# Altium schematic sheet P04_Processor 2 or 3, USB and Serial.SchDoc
size 513 x 386 mm
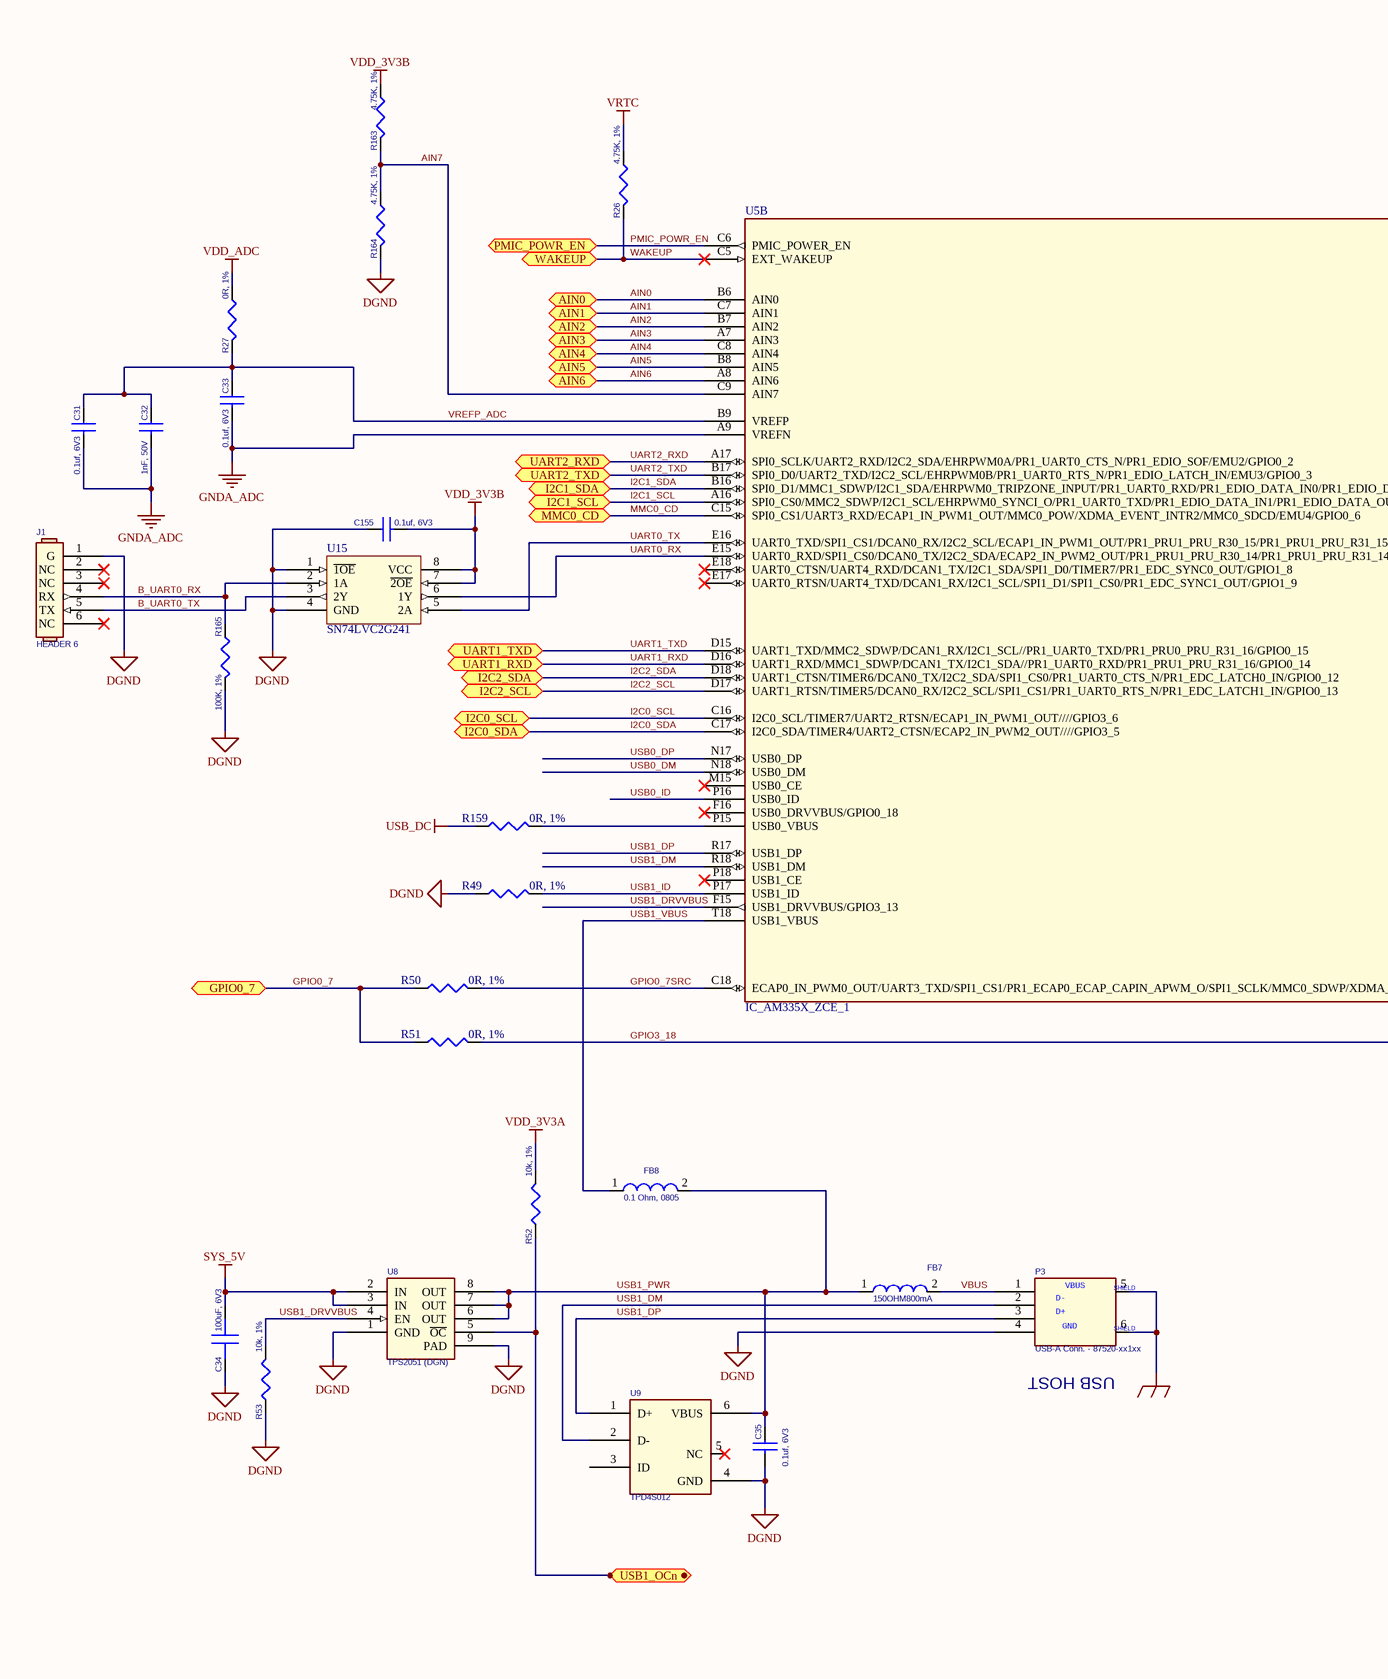
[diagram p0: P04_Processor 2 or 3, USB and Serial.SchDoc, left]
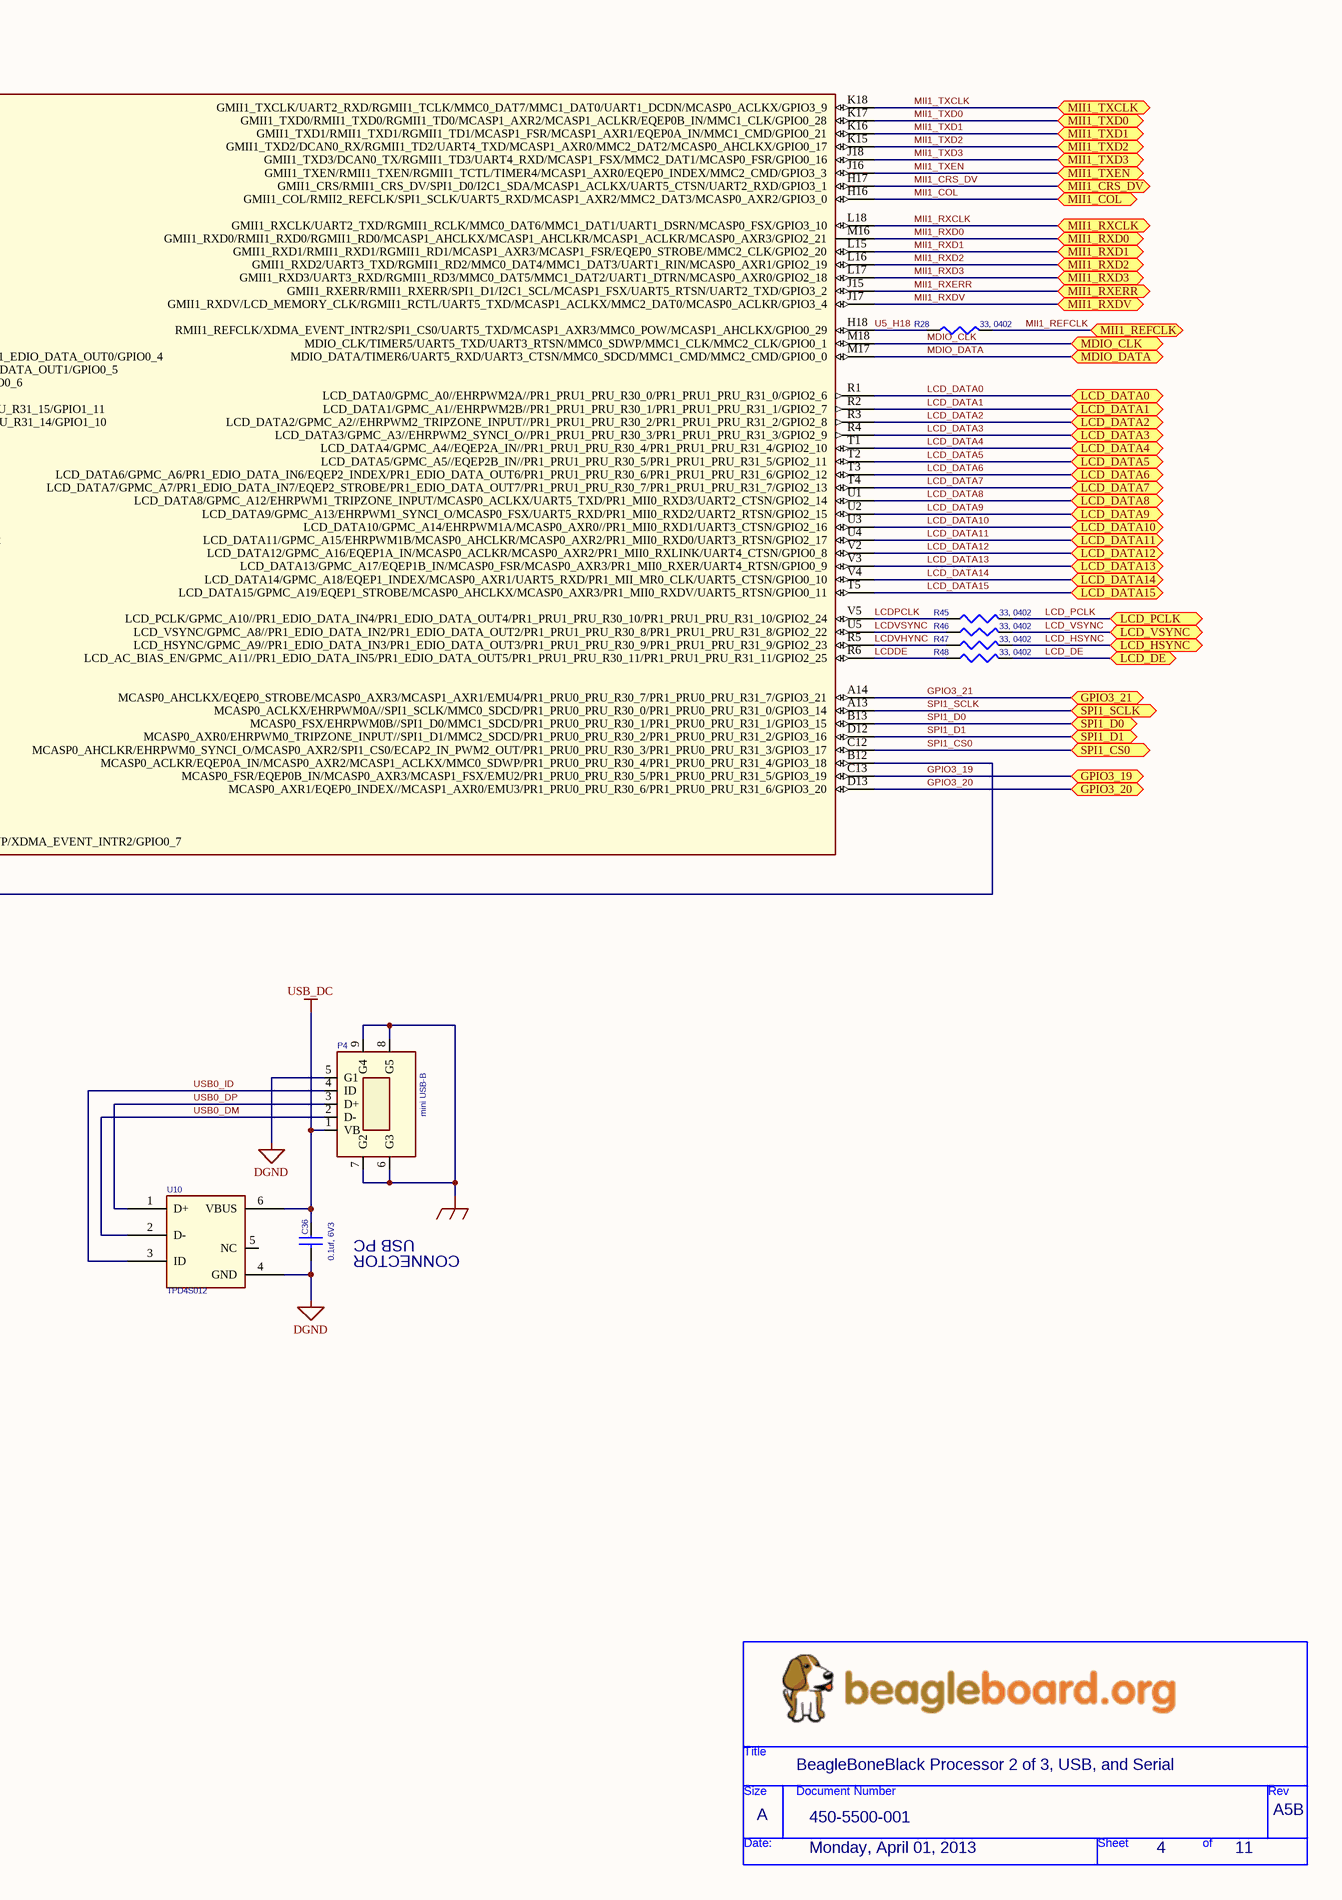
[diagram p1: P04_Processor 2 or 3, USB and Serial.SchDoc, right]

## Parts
*  Page Create Date: Monday, April 01, 2013  Doc: 450-5500-001  RevCode: A5B  Title: BeagleBoneBlack Processor 2 of 3, USB, and Serial  Page Size: A  Page Number: 4  Page Count: 11  (hidden comment: BeagleBoard_org)  (graphical)
C31  0.1uf, 6V3  [402]
C32  1nF, 50V  [402]
C33  0.1uf, 6V3  [402]
C34  100uF, 6V3  [RD205SMD_250D]
C35  0.1uf, 6V3  [402]
C36  0.1uf, 6V3  [402]
C155  0.1uf, 6V3  [402]
FB7  150OHM800mA  [SM-7351-IND-0805]
FB8  0.1 Ohm, 0805  [SM-7351-IND-0805]
J1  HEADER 6  [SIP6]
P3  USB-A Conn. - 87520-xx1xx  [usb_a_sh]
P4  mini USB-B  [USB5MINI_4SHIELDED_SMD-5]
R26  4.75K, 1%  [402]
R27  0R, 1%  [402]
R28  33, 0402  [402]
R45  33, 0402  [402]
R46  33, 0402  [402]
R47  33, 0402  [402]
R48  33, 0402  [402]
R49  0R, 1%  [402]
R50  0R, 1%  [402]
R51  0R, 1%  [402]
R52  10k, 1%  [402]
R53  10k, 1%  [402]
R159  0R, 1%  [402]
R163  4.75K, 1%  [402]
R164  4.75K, 1%  [402]
R165  100K, 1%  [402]
U5  IC_AM335X_ZCE_1  [am33xx_15x15]  (part B of 3)
U8  TPS2051 (DGN)  [DGN-16X60]
U9  TPD4S012  [U_6_DRY]
U10  TPD4S012  [U_6_DRY]
U15  SN74LVC2G241  [U_8_DCU]

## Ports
AIN0, AIN1, AIN2, AIN3, AIN4, AIN5, AIN6, GPIO0_7, GPIO3_19, GPIO3_20, GPIO3_21, I2C0_SCL, I2C0_SDA, I2C1_SCL, I2C1_SDA, I2C2_SCL, I2C2_SDA, LCD_DATA0, LCD_DATA1, LCD_DATA2, LCD_DATA3, LCD_DATA4, LCD_DATA5, LCD_DATA6, LCD_DATA7, LCD_DATA8, LCD_DATA9, LCD_DATA10, LCD_DATA11, LCD_DATA12, LCD_DATA13, LCD_DATA14, LCD_DATA15, LCD_DE, LCD_HSYNC, LCD_PCLK, LCD_VSYNC, MDIO_CLK, MDIO_DATA, MII1_COL, MII1_CRS_DV, MII1_REFCLK, MII1_RXCLK, MII1_RXD0, MII1_RXD1, MII1_RXD2, MII1_RXD3, MII1_RXDV, MII1_RXERR, MII1_TXCLK, MII1_TXD0, MII1_TXD1, MII1_TXD2, MII1_TXD3, MII1_TXEN, MMC0_CD, PMIC_POWR_EN, SPI1_CS0, SPI1_D0, SPI1_D1, SPI1_SCLK, UART1_RXD, UART1_TXD, UART2_RXD, UART2_TXD, USB1_OCn, WAKEUP

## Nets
DGND: C34.2 C35.2 C36.2 C155.1 J1.1(G) P3.4(P4) P4.5(G1) R49.1 R53.2(P2) R164.2 R165.2 U8.1(GND) U8.9(PAD) U9.4(GND) U10.4(GND) U15.1(~{1OE}) U15.4(GND)
GND_EARTH: P3.5(SHELD1) P3.6(PAD4) P4.6(G3) P4.7(G2) P4.8(G5) P4.9(G4)
GNDA_ADC: C31.2 C32.2 C33.2 U5.A9(VREFN)
SYS_5V: C34.1 U8.2(IN) U8.3(IN)
USB_DC: C36.1 P4.1(VB) R159.1 U10.6(VBUS)
VDD_3V3A: R52.1(P1)
VDD_3V3B: C155.2 R163.1 U15.7(~{2OE}) U15.8(VCC)
VDD_ADC: R27.1
VRTC: R26.1
AIN0: U5.B6(AIN0) ; port AIN0
AIN1: U5.C7(AIN1) ; port AIN1
AIN2: U5.B7(AIN2) ; port AIN2
AIN3: U5.A7(AIN3) ; port AIN3
AIN4: U5.C8(AIN4) ; port AIN4
AIN5: U5.B8(AIN5) ; port AIN5
AIN6: U5.A8(AIN6) ; port AIN6
AIN7: R163.2 R164.1 U5.C9(AIN7)
B_UART0_RX: J1.4(RX) R165.1 U15.2(1A)
B_UART0_TX: J1.5(TX) U15.3(2Y)
GPIO0_7: R50.1 R51.1 ; port GPIO0_7
GPIO0_7SRC: R50.2 U5.C18(ECAP0_IN_PWM0_OUT/UART3_TXD/SPI1_CS1/PR1_ECAP0_ECAP_CAPIN_APWM_O/SPI1_SCLK/MMC0_SDWP/XDMA_EVENT_INTR2/GPIO0_7)
GPIO3_18: R51.2 U5.B12(MCASP0_ACLKR/EQEP0A_IN/MCASP0_AXR2/MCASP1_ACLKX/MMC0_SDWP/PR1_PRU0_PRU_R30_4/PR1_PRU0_PRU_R31_4/GPIO3_18)
GPIO3_19: U5.C13(MCASP0_FSR/EQEP0B_IN/MCASP0_AXR3/MCASP1_FSX/EMU2/PR1_PRU0_PRU_R30_5/PR1_PRU0_PRU_R31_5/GPIO3_19) ; port GPIO3_19
GPIO3_20: U5.D13(MCASP0_AXR1/EQEP0_INDEX//MCASP1_AXR0/EMU3/PR1_PRU0_PRU_R30_6/PR1_PRU0_PRU_R31_6/GPIO3_20) ; port GPIO3_20
GPIO3_21: U5.A14(MCASP0_AHCLKX/EQEP0_STROBE/MCASP0_AXR3/MCASP1_AXR1/EMU4/PR1_PRU0_PRU_R30_7/PR1_PRU0_PRU_R31_7/GPIO3_21) ; port GPIO3_21
I2C0_SCL: U5.C16(I2C0_SCL/TIMER7/UART2_RTSN/ECAP1_IN_PWM1_OUT////GPIO3_6) ; port I2C0_SCL
I2C0_SDA: U5.C17(I2C0_SDA/TIMER4/UART2_CTSN/ECAP2_IN_PWM2_OUT////GPIO3_5) ; port I2C0_SDA
I2C1_SCL: U5.A16(SPI0_CS0/MMC2_SDWP/I2C1_SCL/EHRPWM0_SYNCI_O/PR1_UART0_TXD/PR1_EDIO_DATA_IN1/PR1_EDIO_DATA_OUT1/GPIO0_5) ; port I2C1_SCL
I2C1_SDA: U5.B16(SPI0_D1/MMC1_SDWP/I2C1_SDA/EHRPWM0_TRIPZONE_INPUT/PR1_UART0_RXD/PR1_EDIO_DATA_IN0/PR1_EDIO_DATA_OUT0/GPIO0_4) ; port I2C1_SDA
I2C2_SCL: U5.D17(UART1_RTSN/TIMER5/DCAN0_RX/I2C2_SCL/SPI1_CS1/PR1_UART0_RTS_N/PR1_EDC_LATCH1_IN/GPIO0_13) ; port I2C2_SCL
I2C2_SDA: U5.D18(UART1_CTSN/TIMER6/DCAN0_TX/I2C2_SDA/SPI1_CS0/PR1_UART0_CTS_N/PR1_EDC_LATCH0_IN/GPIO0_12) ; port I2C2_SDA
LCD_DATA0: U5.R1(LCD_DATA0/GPMC_A0//EHRPWM2A//PR1_PRU1_PRU_R30_0/PR1_PRU1_PRU_R31_0/GPIO2_6) ; port LCD_DATA0
LCD_DATA1: U5.R2(LCD_DATA1/GPMC_A1//EHRPWM2B//PR1_PRU1_PRU_R30_1/PR1_PRU1_PRU_R31_1/GPIO2_7) ; port LCD_DATA1
LCD_DATA2: U5.R3(LCD_DATA2/GPMC_A2//EHRPWM2_TRIPZONE_INPUT//PR1_PRU1_PRU_R30_2/PR1_PRU1_PRU_R31_2/GPIO2_8) ; port LCD_DATA2
LCD_DATA3: U5.R4(LCD_DATA3/GPMC_A3//EHRPWM2_SYNCI_O//PR1_PRU1_PRU_R30_3/PR1_PRU1_PRU_R31_3/GPIO2_9) ; port LCD_DATA3
LCD_DATA4: U5.T1(LCD_DATA4/GPMC_A4//EQEP2A_IN//PR1_PRU1_PRU_R30_4/PR1_PRU1_PRU_R31_4/GPIO2_10) ; port LCD_DATA4
LCD_DATA5: U5.T2(LCD_DATA5/GPMC_A5//EQEP2B_IN//PR1_PRU1_PRU_R30_5/PR1_PRU1_PRU_R31_5/GPIO2_11) ; port LCD_DATA5
LCD_DATA6: U5.T3(LCD_DATA6/GPMC_A6/PR1_EDIO_DATA_IN6/EQEP2_INDEX/PR1_EDIO_DATA_OUT6/PR1_PRU1_PRU_R30_6/PR1_PRU1_PRU_R31_6/GPIO2_12) ; port LCD_DATA6
LCD_DATA7: U5.T4(LCD_DATA7/GPMC_A7/PR1_EDIO_DATA_IN7/EQEP2_STROBE/PR1_EDIO_DATA_OUT7/PR1_PRU1_PRU_R30_7/PR1_PRU1_PRU_R31_7/GPIO2_13) ; port LCD_DATA7
LCD_DATA8: U5.U1(LCD_DATA8/GPMC_A12/EHRPWM1_TRIPZONE_INPUT/MCASP0_ACLKX/UART5_TXD/PR1_MII0_RXD3/UART2_CTSN/GPIO2_14) ; port LCD_DATA8
LCD_DATA9: U5.U2(LCD_DATA9/GPMC_A13/EHRPWM1_SYNCI_O/MCASP0_FSX/UART5_RXD/PR1_MII0_RXD2/UART2_RTSN/GPIO2_15) ; port LCD_DATA9
LCD_DATA10: U5.U3(LCD_DATA10/GPMC_A14/EHRPWM1A/MCASP0_AXR0//PR1_MII0_RXD1/UART3_CTSN/GPIO2_16) ; port LCD_DATA10
LCD_DATA11: U5.U4(LCD_DATA11/GPMC_A15/EHRPWM1B/MCASP0_AHCLKR/MCASP0_AXR2/PR1_MII0_RXD0/UART3_RTSN/GPIO2_17) ; port LCD_DATA11
LCD_DATA12: U5.V2(LCD_DATA12/GPMC_A16/EQEP1A_IN/MCASP0_ACLKR/MCASP0_AXR2/PR1_MII0_RXLINK/UART4_CTSN/GPIO0_8) ; port LCD_DATA12
LCD_DATA13: U5.V3(LCD_DATA13/GPMC_A17/EQEP1B_IN/MCASP0_FSR/MCASP0_AXR3/PR1_MII0_RXER/UART4_RTSN/GPIO0_9) ; port LCD_DATA13
LCD_DATA14: U5.V4(LCD_DATA14/GPMC_A18/EQEP1_INDEX/MCASP0_AXR1/UART5_RXD/PR1_MII_MR0_CLK/UART5_CTSN/GPIO0_10) ; port LCD_DATA14
LCD_DATA15: U5.T5(LCD_DATA15/GPMC_A19/EQEP1_STROBE/MCASP0_AHCLKX/MCASP0_AXR3/PR1_MII0_RXDV/UART5_RTSN/GPIO0_11) ; port LCD_DATA15
LCD_DE: R48.2 ; port LCD_DE
LCD_HSYNC: R47.2 ; port LCD_HSYNC
LCD_PCLK: R45.2 ; port LCD_PCLK
LCD_VSYNC: R46.2 ; port LCD_VSYNC
LCDDE: R48.1 U5.R6(LCD_AC_BIAS_EN/GPMC_A11//PR1_EDIO_DATA_IN5/PR1_EDIO_DATA_OUT5/PR1_PRU1_PRU_R30_11/PR1_PRU1_PRU_R31_11/GPIO2_25)
LCDPCLK: R45.1 U5.V5(LCD_PCLK/GPMC_A10//PR1_EDIO_DATA_IN4/PR1_EDIO_DATA_OUT4/PR1_PRU1_PRU_R30_10/PR1_PRU1_PRU_R31_10/GPIO2_24)
LCDVHYNC: R47.1 U5.R5(LCD_HSYNC/GPMC_A9//PR1_EDIO_DATA_IN3/PR1_EDIO_DATA_OUT3/PR1_PRU1_PRU_R30_9/PR1_PRU1_PRU_R31_9/GPIO2_23)
LCDVSYNC: R46.1 U5.U5(LCD_VSYNC/GPMC_A8//PR1_EDIO_DATA_IN2/PR1_EDIO_DATA_OUT2/PR1_PRU1_PRU_R30_8/PR1_PRU1_PRU_R31_8/GPIO2_22)
MDIO_CLK: U5.M18(MDIO_CLK/TIMER5/UART5_TXD/UART3_RTSN/MMC0_SDWP/MMC1_CLK/MMC2_CLK/GPIO0_1) ; port MDIO_CLK
MDIO_DATA: U5.M17(MDIO_DATA/TIMER6/UART5_RXD/UART3_CTSN/MMC0_SDCD/MMC1_CMD/MMC2_CMD/GPIO0_0) ; port MDIO_DATA
MII1_COL: U5.H16(GMII1_COL/RMII2_REFCLK/SPI1_SCLK/UART5_RXD/MCASP1_AXR2/MMC2_DAT3/MCASP0_AXR2/GPIO3_0) ; port MII1_COL
MII1_CRS_DV: U5.H17(GMII1_CRS/RMII1_CRS_DV/SPI1_D0/I2C1_SDA/MCASP1_ACLKX/UART5_CTSN/UART2_RXD/GPIO3_1) ; port MII1_CRS_DV
MII1_REFCLK: R28.2 ; port MII1_REFCLK
MII1_RXCLK: U5.L18(GMII1_RXCLK/UART2_TXD/RGMII1_RCLK/MMC0_DAT6/MMC1_DAT1/UART1_DSRN/MCASP0_FSX/GPIO3_10) ; port MII1_RXCLK
MII1_RXD0: U5.M16(GMII1_RXD0/RMII1_RXD0/RGMII1_RD0/MCASP1_AHCLKX/MCASP1_AHCLKR/MCASP1_ACLKR/MCASP0_AXR3/GPIO2_21) ; port MII1_RXD0
MII1_RXD1: U5.L15(GMII1_RXD1/RMII1_RXD1/RGMII1_RD1/MCASP1_AXR3/MCASP1_FSR/EQEP0_STROBE/MMC2_CLK/GPIO2_20) ; port MII1_RXD1
MII1_RXD2: U5.L16(GMII1_RXD2/UART3_TXD/RGMII1_RD2/MMC0_DAT4/MMC1_DAT3/UART1_RIN/MCASP0_AXR1/GPIO2_19) ; port MII1_RXD2
MII1_RXD3: U5.L17(GMII1_RXD3/UART3_RXD/RGMII1_RD3/MMC0_DAT5/MMC1_DAT2/UART1_DTRN/MCASP0_AXR0/GPIO2_18) ; port MII1_RXD3
MII1_RXDV: U5.J17(GMII1_RXDV/LCD_MEMORY_CLK/RGMII1_RCTL/UART5_TXD/MCASP1_ACLKX/MMC2_DAT0/MCASP0_ACLKR/GPIO3_4) ; port MII1_RXDV
MII1_RXERR: U5.J15(GMII1_RXERR/RMII1_RXERR/SPI1_D1/I2C1_SCL/MCASP1_FSX/UART5_RTSN/UART2_TXD/GPIO3_2) ; port MII1_RXERR
MII1_TXCLK: U5.K18(GMII1_TXCLK/UART2_RXD/RGMII1_TCLK/MMC0_DAT7/MMC1_DAT0/UART1_DCDN/MCASP0_ACLKX/GPIO3_9) ; port MII1_TXCLK
MII1_TXD0: U5.K17(GMII1_TXD0/RMII1_TXD0/RGMII1_TD0/MCASP1_AXR2/MCASP1_ACLKR/EQEP0B_IN/MMC1_CLK/GPIO0_28) ; port MII1_TXD0
MII1_TXD1: U5.K16(GMII1_TXD1/RMII1_TXD1/RGMII1_TD1/MCASP1_FSR/MCASP1_AXR1/EQEP0A_IN/MMC1_CMD/GPIO0_21) ; port MII1_TXD1
MII1_TXD2: U5.K15(GMII1_TXD2/DCAN0_RX/RGMII1_TD2/UART4_TXD/MCASP1_AXR0/MMC2_DAT2/MCASP0_AHCLKX/GPIO0_17) ; port MII1_TXD2
MII1_TXD3: U5.J18(GMII1_TXD3/DCAN0_TX/RGMII1_TD3/UART4_RXD/MCASP1_FSX/MMC2_DAT1/MCASP0_FSR/GPIO0_16) ; port MII1_TXD3
MII1_TXEN: U5.J16(GMII1_TXEN/RMII1_TXEN/RGMII1_TCTL/TIMER4/MCASP1_AXR0/EQEP0_INDEX/MMC2_CMD/GPIO3_3) ; port MII1_TXEN
MMC0_CD: U5.C15(SPI0_CS1/UART3_RXD/ECAP1_IN_PWM1_OUT/MMC0_POW/XDMA_EVENT_INTR2/MMC0_SDCD/EMU4/GPIO0_6) ; port MMC0_CD
PMIC_POWR_EN: U5.C6(PMIC_POWER_EN) ; port PMIC_POWR_EN
SPI1_CS0: U5.C12(MCASP0_AHCLKR/EHRPWM0_SYNCI_O/MCASP0_AXR2/SPI1_CS0/ECAP2_IN_PWM2_OUT/PR1_PRU0_PRU_R30_3/PR1_PRU0_PRU_R31_3/GPIO3_17) ; port SPI1_CS0
SPI1_D0: U5.B13(MCASP0_FSX/EHRPWM0B//SPI1_D0/MMC1_SDCD/PR1_PRU0_PRU_R30_1/PR1_PRU0_PRU_R31_1/GPIO3_15) ; port SPI1_D0
SPI1_D1: U5.D12(MCASP0_AXR0/EHRPWM0_TRIPZONE_INPUT//SPI1_D1/MMC2_SDCD/PR1_PRU0_PRU_R30_2/PR1_PRU0_PRU_R31_2/GPIO3_16) ; port SPI1_D1
SPI1_SCLK: U5.A13(MCASP0_ACLKX/EHRPWM0A//SPI1_SCLK/MMC0_SDCD/PR1_PRU0_PRU_R30_0/PR1_PRU0_PRU_R31_0/GPIO3_14) ; port SPI1_SCLK
U5_H18: R28.1 U5.H18(RMII1_REFCLK/XDMA_EVENT_INTR2/SPI1_CS0/UART5_TXD/MCASP1_AXR3/MMC0_POW/MCASP1_AHCLKX/GPIO0_29)
UART0_RX: U5.E15(UART0_RXD/SPI1_CS0/DCAN0_TX/I2C2_SDA/ECAP2_IN_PWM2_OUT/PR1_PRU1_PRU_R30_14/PR1_PRU1_PRU_R31_14/GPIO1_10) U15.6(1Y)
UART0_TX: U5.E16(UART0_TXD/SPI1_CS1/DCAN0_RX/I2C2_SCL/ECAP1_IN_PWM1_OUT/PR1_PRU1_PRU_R30_15/PR1_PRU1_PRU_R31_15/GPIO1_11) U15.5(2A)
UART1_RXD: U5.D16(UART1_RXD/MMC1_SDWP/DCAN1_TX/I2C1_SDA//PR1_UART0_RXD/PR1_PRU1_PRU_R31_16/GPIO0_14) ; port UART1_RXD
UART1_TXD: U5.D15(UART1_TXD/MMC2_SDWP/DCAN1_RX/I2C1_SCL//PR1_UART0_TXD/PR1_PRU0_PRU_R31_16/GPIO0_15) ; port UART1_TXD
UART2_RXD: U5.A17(SPI0_SCLK/UART2_RXD/I2C2_SDA/EHRPWM0A/PR1_UART0_CTS_N/PR1_EDIO_SOF/EMU2/GPIO0_2) ; port UART2_RXD
UART2_TXD: U5.B17(SPI0_D0/UART2_TXD/I2C2_SCL/EHRPWM0B/PR1_UART0_RTS_N/PR1_EDIO_LATCH_IN/EMU3/GPIO0_3) ; port UART2_TXD
USB0_DM: P4.2(D-) U5.N18(USB0_DM) U10.2(D-)
USB0_DP: P4.3(D+) U5.N17(USB0_DP) U10.1(D+)
USB0_ID: P4.4(ID) U5.P16(USB0_ID) U10.3(ID)
USB1_DM: P3.2(P2) U5.R18(USB1_DM) U9.2(D-)
USB1_DP: P3.3(P3) U5.R17(USB1_DP) U9.1(D+)
USB1_DRVVBUS: R53.1(P1) U5.F15(USB1_DRVVBUS/GPIO3_13) U8.4(EN)
USB1_ID: R49.2 U5.P17(USB1_ID)
USB1_OCn: R52.2(P2) U8.5(~{OC}) ; port USB1_OCn
USB1_PWR: C35.1 FB7.1 FB8.2 U8.6(OUT) U8.7(OUT) U8.8(OUT) U9.6(VBUS)
USB1_VBUS: FB8.1 U5.T18(USB1_VBUS)
VBUS: FB7.2 P3.1(P1)
VREFP_ADC: C31.1 C32.1 C33.1 R27.2 U5.B9(VREFP)
WAKEUP: R26.2 U5.C5(EXT_WAKEUP) ; port WAKEUP
NetR159_2: R159.2 U5.P15(USB0_VBUS)

Not connected (* = marked no-connect by the designer): J1 2(NC)* 3(NC)* 6(NC)*; U5 E17(UART0_RTSN/UART4_TXD/DCAN1_RX/I2C1_SCL/SPI1_D1/SPI1_CS0/PR1_EDC_SYNC1_OUT/GPIO1_9)* E18(UART0_CTSN/UART4_RXD/DCAN1_TX/I2C1_SDA/SPI1_D0/TIMER7/PR1_EDC_SYNC0_OUT/GPIO1_8)* F16(USB0_DRVVBUS/GPIO0_18)* M15(USB0_CE)* P18(USB1_CE)*; U9 3(ID) 5(NC)*; U10 5(NC)

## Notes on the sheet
- (near P3) USB HOST
- USB PC
- CONNECTOR

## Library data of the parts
C31 C33 C35 C36 C155 = CAP_0.1uF_X7R_16V_10% 0402: CAP CER 0.1UF 6.3V 10% X5R 0402; Manufacturer: TDK Corporation; Manufacturer Part Number: C1005X5R0J104K050BA; Capacitance: 0.1µF
C32 = CAP_0.001_X7R_50V_5%_0402: CAP CER 1000PF 16V 10% X7R 0402; Manufacturer: Yageo; Manufacturer Part Number: CC0402KRX7R7BB102
C34 = CAP SMD: CAP ALUM 100UF 6.3V 20% SMD; Manufacturer: Cornell Dubilier Electronics (CDE); Manufacturer Part Number: AVE107M06D16T-F; Capacitance: 100µF; Lifetime @ Temp.: 2000 Hrs @ 85°C; Ripple Current: 120mA; ESR (Equivalent Series Resistance): 4.64 Ohm; Surface Mount Land Size: 0.260" L x 0.260" W (6.60mm x 6.60mm)
FB7 = FER_180_200_0: FERRITE 800MA 150 OHM 0805 SMD; PartName: FerriteBead150ohm800mA; Mfr: Steward; MfrNum: LI0805H151R-10; TIIntPartnumber: 1L0010; Manufacturer: Laird-Signal Integrity Products; Vendor: Digikey; Impedance @ Frequency: 150 Ohm @ 100MHz; DC Resistance (DCR): 150 mOhm Max; Filter Type: Differential Mode - Single
FB8 = FER_180_200_0: RES .10 OHM 1/8W 5% 0805; Manufacturer: CTS Resistor Products; Manufacturer Part Number: 73L3R10J; Resistance (Ohms): 0.1; Power (Watts): 0.125W, 1/8W; Temperature Coefficient: ±200ppm/°C
J1 = HDR_6x1: CONN HEADER 6POS, VERTICAL,  .100 STR TIN; Manufacturer: Samtec Inc; Manufacturer Part Number: FTR-110-03-G-D-06; Connector Type: Unshrouded; Number of Positions: 20; Number of Positions Loaded: 19; Pitch: 0.050" (1.27mm); Row Spacing: 0.100" (2.54mm)
P3 = CONN_54819-0578_2: CONN RCPT USB TYPE A R/A PCB; Manufacturer: FCI; Manufacturer Part Number: 87520-0010BLF; CLASS: IO; TN: 224-0234-000; Number of Contacts: 4; Gender: Receptacle; Specifications: USB 2.0
P4 = MINI-USB-AB-SOCKET: CONN RCPT USB MINI B R/A SMD; Manufacturer: KYCON; Manufacturer Part Number: 0565790576; Order# 2: C-440247; ATLStockNo1: 4500.0223; Order#: KMAB-SMT-5S-S-30TR; Connector Type: USB - mini AB; Number of Contacts: 5; Gender: Receptacle; Specifications: USB 2.0 OTG
R26 R163 R164 = RES_4.75K_1/16W_1%_0402: RES 4.75K OHM 1/16W 1% 0402 SMD; Manufacturer: Stackpole Electronics Inc; Manufacturer Part Number: RMCF0402FT4K75; Power (Watts): 0.063W, 1/16W; Temperature Coefficient: ±100ppm/°C
R27 = RES_0_1/16W_1%_0402: RES 0.0 OHM 1/16W 0402 SMD; Manufacturer: Yageo; Manufacturer Part Number: RC0402JR-070RL; Resistance (Ohms): 0.0; Power (Watts): 0.063W, 1/16W; Tolerance: Jumper
R28 R45-R48 = RES_33_0402: RES 33 OHM 1/16W 5% 0402 SMD; Manufacturer: Panasonic Electronic Components; Manufacturer Part Number: ERJ-2GEJ330X; Resistance (Ohms): 33; Power (Watts): 0.1W, 1/10W; Temperature Coefficient: ±200ppm/°C
R49-R51 R159 = RES_0_1/16W_1%_0402: RES 0.0 OHM 1/16W 0402 SMD; Manufacturer: Yageo; Manufacturer Part Number: RC0402JR-070RL; Power (Watts): 0.063W, 1/16W; Resistance (Ohms): 0.0; Tolerance: Jumper
R52 R53 = RES SMD: RES 10K OHM 1/16W 5% 0402 SMD; Manufacturer: Rohm Semiconductor; Manufacturer Part Number: MCR01MZPJ103; Power (Watts): 0.063W, 1/16W; Temperature Coefficient: ±200ppm/°C
R165 = RES_100K_1/16W_1%_0402: RES 100K OHM 1/16W 1% 0402 SMD; Manufacturer: Stackpole Electronics Inc; Manufacturer Part Number: RMCF0402FT100K; Power (Watts): 0.063W, 1/16W; Temperature Coefficient: ±100ppm/°C
U5 = IC_AM335X_ZCE_1: SubArctic Cortex A8 Processor 15x15; PartName: AM335X_15x15; Mfr: TI; MfrNum: AM335x 15x15 FBGA ZCE; TIIntPartnumber: 1A0242; Manufacturer: Texas Instruments; Manufacturer Part Number: XAM3359ZCZ; Vendor: Arrow; Cost100: 10.00; Processor Type: ARM Microprocessor; Voltage: 1.06 V ~ 1.15 V
U8 = TPS2061_0: IC 1.5A PWR DIST SWITCH 8-SOIC; Manufacturer: Texas Instruments; Manufacturer Part Number: TPS2051BDGNR; Number of Outputs: 1; Rds (On): 135 mOhm; Internal Switch(s): Yes; Current Limit: 1A; Voltage - Input: 2.7 V ~ 5.5 V
U9 U10 = PROT_TPD4S012: ESD 4channel USB Interface; Mfr: TI; MfrNum: TPD4S012DRY; TIIntPartnumber: 1A0233; Manufacturer: Texas Instruments; Manufacturer Part Number: TPD4S012DRYR; Vendor: Digikey; Cost100: 0.76; Cost10K: 0.23; Power (Watts): 60W; Number of Circuits: 4
U15 = SN74LVC2G241: IC BUFF/DVR TRI-ST DL 8VSSOP; Manufacturer: Texas Instruments; Manufacturer Part Number: SN74LVC2G241DCUR; Logic Type: Buffer/Line Driver, Non-Inverting; Number of Elements: 2; Number of Bits per Element: 1; Current - Output High, Low: 32mA, 32mA; Voltage - Supply: 1.65 V ~ 5.5 V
